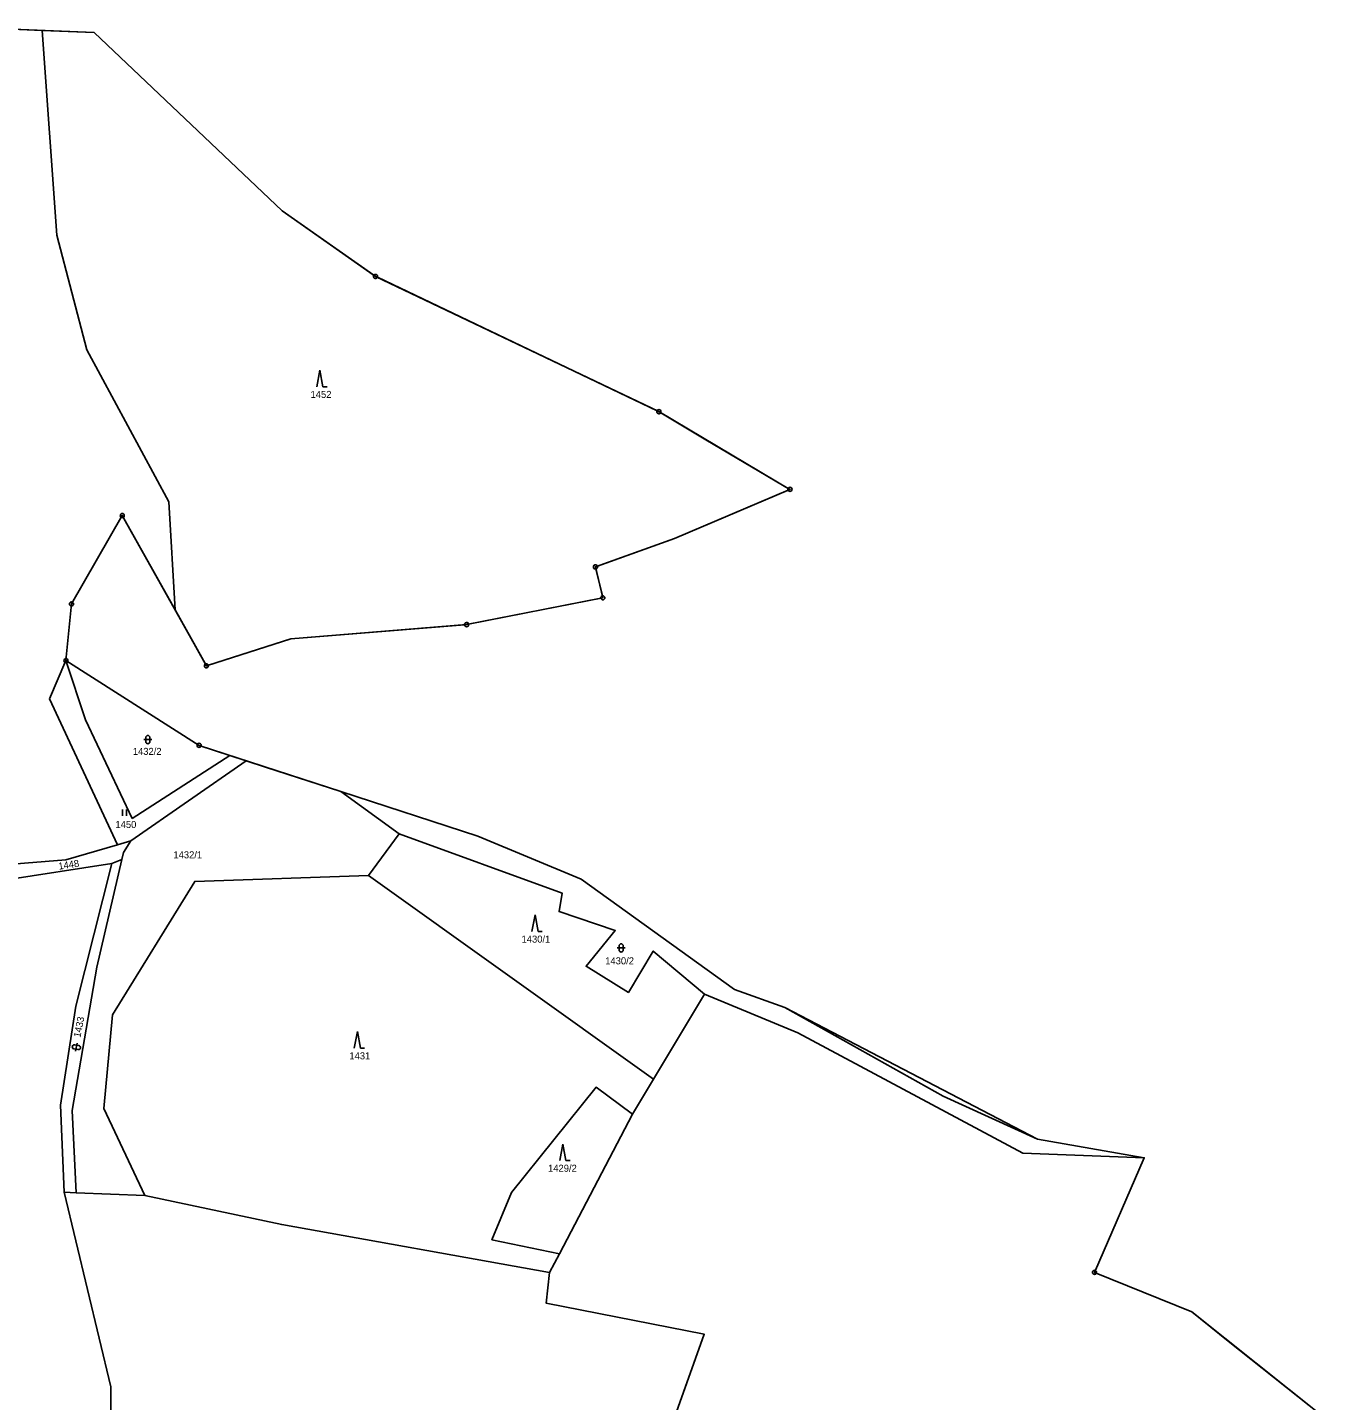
# Model space of a CAD drawing. Extents: x -760642 to -757221, y -1092371 to -1088855.
# Drawn here: x -758872.5 to -758559.6, y -1090656.5 to -1090324.2 of the extents above; entities that cross this region are included whole.
import ezdxf

# ---------------------------------------------------------------- set-up
doc = ezdxf.new("R2010")
doc.units = 0
for name, color, linetype in [('Vrstva 1', 7, 'Continuous'), ('Vrstva 13', 7, 'Continuous'), ('Vrstva 18', 7, 'Continuous'), ('Vrstva 24', 7, 'Continuous'), ('Vrstva 25', 7, 'Continuous'), ('Vrstva 28', 7, 'Continuous'), ('Vrstva 30', 7, 'Continuous')]:
    doc.layers.add(name, color=color, linetype=linetype)

msp = doc.modelspace()

# ---------------------------------------------------------------- linework, layer by layer
at = {"layer": 'Vrstva 1'}
for p, q in [((-758868.91, -1090324.89), (-758865.38, -1090374.41)), ((-758865.38, -1090374.41), (-758858.08, -1090402.2)), ((-758858.08, -1090402.2), (-758838.3, -1090438.95)), ((-758838.3, -1090438.95), (-758836.74, -1090465.14)), ((-758863.16, -1090477.4), (-758867.15, -1090486.69)), ((-758863.16, -1090477.4), (-758858.44, -1090491.77)), ((-758867.15, -1090486.69), (-758850.72, -1090521.98)), ((-758858.44, -1090491.77), (-758847.13, -1090515.61)), ((-758847.13, -1090515.61), (-758823.48, -1090500.36)), ((-758819.57, -1090501.63), (-758847.49, -1090521.03)), ((-758782.53, -1090519.32), (-758796.68, -1090509.09)), ((-758850.72, -1090521.98), (-758847.49, -1090521.03)), ((-758847.49, -1090521.03), (-758849.27, -1090523.84)), ((-758782.53, -1090519.32), (-758789.94, -1090529.44)), ((-758743.09, -1090533.73), (-758782.53, -1090519.32)), ((-758863.21, -1090525.65), (-758850.72, -1090521.98)), ((-758849.27, -1090523.84), (-758849.67, -1090525.57)), ((-758878.15, -1090526.82), (-758863.21, -1090525.65)), ((-758878.13, -1090530.58), (-758852.04, -1090526.51)), ((-758852.04, -1090526.51), (-758860.78, -1090561.07)), ((-758849.67, -1090525.57), (-758855.66, -1090551.59)), ((-758852.04, -1090526.51), (-758849.67, -1090525.57)), ((-758832, -1090530.87), (-758851.93, -1090563.12)), ((-758832, -1090530.87), (-758789.94, -1090529.44)), ((-758789.94, -1090529.44), (-758721.01, -1090578.75)), ((-758743.09, -1090533.73), (-758743.83, -1090538.15)), ((-758743.83, -1090538.15), (-758730.25, -1090542.74)), ((-758730.25, -1090542.74), (-758737.32, -1090551.37)), ((-758721.07, -1090547.7), (-758727.08, -1090557.7)), ((-758721.07, -1090547.7), (-758708.68, -1090558.15)), ((-758855.66, -1090551.59), (-758861.69, -1090586.26)), ((-758737.32, -1090551.37), (-758727.08, -1090557.7)), ((-758708.68, -1090558.15), (-758721.01, -1090578.75)), ((-758708.68, -1090558.15), (-758686.04, -1090567.49)), ((-758860.78, -1090561.07), (-758864.45, -1090585.04)), ((-758851.93, -1090563.12), (-758854, -1090585.82)), ((-758686.04, -1090567.49), (-758631.64, -1090596.66)), ((-758755.34, -1090606.13), (-758734.88, -1090580.69)), ((-758734.88, -1090580.69), (-758726.08, -1090587.22)), ((-758721.01, -1090578.75), (-758726.08, -1090587.22)), ((-758864.45, -1090585.04), (-758863.61, -1090606.09)), ((-758861.69, -1090586.26), (-758860.66, -1090606.2)), ((-758854, -1090585.82), (-758844.04, -1090606.85)), ((-758726.08, -1090587.22), (-758743.77, -1090621)), ((-758631.64, -1090596.66), (-758602.28, -1090597.75)), ((-758863.61, -1090606.09), (-758852.28, -1090653.15)), ((-758860.66, -1090606.2), (-758863.61, -1090606.09)), ((-758844.04, -1090606.85), (-758860.66, -1090606.2)), ((-758844.04, -1090606.85), (-758810.96, -1090613.91)), ((-758760.08, -1090617.58), (-758755.34, -1090606.13)), ((-758810.96, -1090613.91), (-758746.18, -1090625.5)), ((-758743.77, -1090621), (-758760.08, -1090617.58)), ((-758746.18, -1090625.5), (-758743.77, -1090621)), ((-758746.18, -1090625.5), (-758746.95, -1090632.96)), ((-758746.95, -1090632.96), (-758708.72, -1090640.47)), ((-758708.72, -1090640.47), (-758723.71, -1090682.53)), ((-758852.28, -1090653.15), (-758852.35, -1090686.17))]:
    msp.add_line(p, q, dxfattribs=at)
at = {"layer": 'Vrstva 13'}
for p, q in [((-758885.97, -1090324.17), (-758868.91, -1090324.89)), ((-758868.91, -1090324.89), (-758856.34, -1090325.42)), ((-758856.34, -1090325.42), (-758810.83, -1090368.56)), ((-758810.83, -1090368.56), (-758788.26, -1090384.43)), ((-758788.26, -1090384.43), (-758719.69, -1090417.15)), ((-758719.69, -1090417.15), (-758708.32, -1090424.01)), ((-758708.32, -1090424.01), (-758687.98, -1090435.97)), ((-758687.98, -1090435.97), (-758715.88, -1090447.87)), ((-758849.53, -1090442.3), (-758861.82, -1090463.69)), ((-758849.53, -1090442.3), (-758836.74, -1090465.14)), ((-758715.88, -1090447.87), (-758735.04, -1090454.73)), ((-758735.04, -1090454.73), (-758733.26, -1090462.21)), ((-758861.82, -1090463.69), (-758863.16, -1090477.4)), ((-758733.26, -1090462.21), (-758766.23, -1090468.7)), ((-758836.74, -1090465.14), (-758829.17, -1090478.68)), ((-758766.23, -1090468.7), (-758808.75, -1090472.12)), ((-758808.75, -1090472.12), (-758829.17, -1090478.68)), ((-758863.16, -1090477.4), (-758830.94, -1090497.93)), ((-758830.94, -1090497.93), (-758823.48, -1090500.36)), ((-758823.48, -1090500.36), (-758819.57, -1090501.63)), ((-758819.57, -1090501.63), (-758814.86, -1090503.17)), ((-758814.86, -1090503.17), (-758796.68, -1090509.09)), ((-758796.68, -1090509.09), (-758763.51, -1090519.9)), ((-758763.51, -1090519.9), (-758738.51, -1090530.3)), ((-758738.51, -1090530.3), (-758701.38, -1090557.05)), ((-758701.38, -1090557.05), (-758689.24, -1090561.38)), ((-758689.24, -1090561.38), (-758650.92, -1090582.86)), ((-758650.92, -1090582.86), (-758628.1, -1090593.26)), ((-758628.1, -1090593.26), (-758602.28, -1090597.75)), ((-758602.28, -1090597.75), (-758614.29, -1090625.47)), ((-758614.29, -1090625.47), (-758590.74, -1090634.99)), ((-758590.74, -1090634.99), (-758581.97, -1090642.09)), ((-758581.97, -1090642.09), (-758559.61, -1090659.84))]:
    msp.add_line(p, q, dxfattribs=at)
at = {"layer": 'Vrstva 24'}
for centre, radius in [((-758788.26, -1090384.43), 0.5), ((-758788.26, -1090384.43), 0.0327), ((-758719.69, -1090417.15), 0.5), ((-758719.69, -1090417.15), 0.0327), ((-758687.98, -1090435.97), 0.5), ((-758687.98, -1090435.97), 0.0327), ((-758849.53, -1090442.3), 0.5), ((-758849.53, -1090442.3), 0.0327), ((-758735.04, -1090454.73), 0.5), ((-758735.04, -1090454.73), 0.0327), ((-758861.82, -1090463.69), 0.5), ((-758861.82, -1090463.69), 0.0327), ((-758733.26, -1090462.21), 0.5), ((-758733.26, -1090462.21), 0.0327), ((-758766.23, -1090468.7), 0.5), ((-758766.23, -1090468.7), 0.0327), ((-758863.16, -1090477.4), 0.5), ((-758863.16, -1090477.4), 0.0327), ((-758829.17, -1090478.68), 0.5), ((-758829.17, -1090478.68), 0.0327), ((-758830.94, -1090497.93), 0.5), ((-758830.94, -1090497.93), 0.0327), ((-758614.29, -1090625.47), 0.5), ((-758614.29, -1090625.47), 0.0327)]:
    msp.add_circle(centre, radius, dxfattribs=at)
at = {"layer": 'Vrstva 25'}
for p, q in [((-758801.702, -1090407.119), (-758802.435, -1090411.119)), ((-758801.702, -1090407.119), (-758800.969, -1090411.119)), ((-758800.969, -1090411.119), (-758799.969, -1090411.119)), ((-758844.34, -1090496.53), (-758842.34, -1090496.53)), ((-758843.84, -1090497.03), (-758843.84, -1090496.03)), ((-758842.84, -1090497.03), (-758842.84, -1090496.03)), ((-758849.507, -1090513.485), (-758849.507, -1090514.985)), ((-758848.485, -1090514.985), (-758848.485, -1090513.485)), ((-758749.662, -1090538.959), (-758750.395, -1090542.959)), ((-758749.662, -1090538.959), (-758748.929, -1090542.959)), ((-758748.929, -1090542.959), (-758747.929, -1090542.959)), ((-758729.82, -1090546.95), (-758727.82, -1090546.95)), ((-758729.32, -1090547.45), (-758729.32, -1090546.45)), ((-758728.32, -1090547.45), (-758728.32, -1090546.45)), ((-758792.652, -1090567.209), (-758793.385, -1090571.209)), ((-758792.652, -1090567.209), (-758791.919, -1090571.209)), ((-758860.052, -1090570.592), (-758861.033, -1090570.396)), ((-758860.837, -1090571.964), (-758860.444, -1090570.003)), ((-758860.248, -1090571.572), (-758861.229, -1090571.376)), ((-758791.919, -1090571.209), (-758790.919, -1090571.209)), ((-758742.912, -1090594.409), (-758743.645, -1090598.409)), ((-758742.912, -1090594.409), (-758742.179, -1090598.409)), ((-758742.179, -1090598.409), (-758741.179, -1090598.409))]:
    msp.add_line(p, q, dxfattribs=at)
for centre, start, end in [((-758843.34, -1090496.03), 0, 180), ((-758843.34, -1090497.03), 180, 0), ((-758728.82, -1090546.45), 0, 180), ((-758728.82, -1090547.45), 180, 0), ((-758861.131, -1090570.886), 78.68997, 258.68997), ((-758860.15, -1090571.082), 258.68997, 78.68997)]:
    msp.add_arc(centre, 0.5, start, end, dxfattribs=at)
at = {"layer": 'Vrstva 28'}
msp.add_lwpolyline([(-758885.97, -1090324.17), (-758856.34, -1090325.42), (-758810.83, -1090368.56), (-758788.26, -1090384.43), (-758719.69, -1090417.15), (-758687.98, -1090435.97), (-758715.88, -1090447.87), (-758735.04, -1090454.73), (-758733.26, -1090462.21), (-758766.23, -1090468.7), (-758808.75, -1090472.12), (-758829.17, -1090478.68), (-758849.53, -1090442.3), (-758861.82, -1090463.69), (-758863.16, -1090477.4), (-758830.94, -1090497.93), (-758796.68, -1090509.09), (-758763.51, -1090519.9), (-758738.51, -1090530.3), (-758701.38, -1090557.05), (-758689.24, -1090561.38), (-758628.1, -1090593.26), (-758602.28, -1090597.75), (-758614.29, -1090625.47), (-758590.74, -1090634.99), (-758559.61, -1090659.84)], dxfattribs=at)
at = {"layer": 'Vrstva 30'}
for points in [[(-758788.669, -1090384.142), (-758810.83, -1090368.56), (-758856.34, -1090325.42), (-758868.91, -1090324.89), (-758865.38, -1090374.41), (-758858.08, -1090402.2), (-758838.3, -1090438.95), (-758836.74, -1090465.14), (-758829.414, -1090478.244)], [(-758720.141, -1090416.935), (-758787.809, -1090384.645)], [(-758688.411, -1090435.717), (-758708.32, -1090424.01), (-758719.262, -1090417.408)], [(-758734.569, -1090454.561), (-758715.88, -1090447.87), (-758688.44, -1090436.166)], [(-758733.376, -1090461.724), (-758734.924, -1090455.216)], [(-758765.739, -1090468.603), (-758733.751, -1090462.307)], [(-758828.694, -1090478.527), (-758808.75, -1090472.12), (-758766.728, -1090468.74)], [(-758816.526, -1090502.625), (-758819.571, -1090501.633), (-758819.574, -1090501.633), (-758847.49, -1090521.03), (-758849.27, -1090523.84), (-758849.67, -1090525.57), (-758855.66, -1090551.59), (-758861.69, -1090586.26), (-758860.66, -1090606.2), (-758844.04, -1090606.85), (-758854, -1090585.82), (-758851.93, -1090563.12), (-758832, -1090530.87), (-758789.94, -1090529.44), (-758782.53, -1090519.32), (-758796.68, -1090509.09), (-758814.86, -1090503.17), (-758816.526, -1090502.625)], [(-758743.09, -1090533.73), (-758743.83, -1090538.15), (-758730.25, -1090542.74), (-758737.32, -1090551.37), (-758727.08, -1090557.7), (-758721.07, -1090547.7), (-758708.68, -1090558.15), (-758686.04, -1090567.49), (-758631.64, -1090596.66), (-758602.28, -1090597.75), (-758628.1, -1090593.26), (-758650.92, -1090582.86), (-758689.24, -1090561.38), (-758701.38, -1090557.05), (-758738.51, -1090530.3), (-758763.51, -1090519.9), (-758796.68, -1090509.09), (-758782.53, -1090519.32), (-758743.09, -1090533.73)], [(-758789.94, -1090529.44), (-758721.01, -1090578.75), (-758708.68, -1090558.15), (-758721.07, -1090547.7), (-758727.08, -1090557.7), (-758737.32, -1090551.37), (-758730.25, -1090542.74), (-758743.83, -1090538.15), (-758743.09, -1090533.73), (-758782.53, -1090519.32), (-758789.94, -1090529.44)], [(-758760.08, -1090617.58), (-758755.34, -1090606.13), (-758734.88, -1090580.69), (-758726.08, -1090587.22), (-758721.01, -1090578.75), (-758789.94, -1090529.44), (-758832, -1090530.87), (-758851.93, -1090563.12), (-758854, -1090585.82), (-758844.04, -1090606.85), (-758810.96, -1090613.91), (-758746.18, -1090625.5), (-758743.77, -1090621), (-758760.08, -1090617.58)], [(-758734.88, -1090580.69), (-758755.34, -1090606.13), (-758760.08, -1090617.58), (-758743.77, -1090621), (-758726.08, -1090587.22), (-758734.88, -1090580.69)], [(-758821.37, -1090721.67), (-758776.27, -1090726.57), (-758733.29, -1090731.24), (-758725.99, -1090687.96), (-758723.71, -1090682.53), (-758708.72, -1090640.47), (-758746.95, -1090632.96), (-758746.18, -1090625.5), (-758810.96, -1090613.91), (-758844.04, -1090606.85), (-758860.66, -1090606.2), (-758863.61, -1090606.09), (-758852.28, -1090653.15), (-758852.35, -1090686.17), (-758854.21, -1090708.78), (-758858.33, -1090718.54), (-758856.01, -1090718.74), (-758821.37, -1090721.67)]]:
    msp.add_lwpolyline(points, dxfattribs=at)
for centre, start, end in [((-758788.26, -1090384.43), 144.88719, 180), ((-758788.26, -1090384.43), 180, 334.49062), ((-758719.69, -1090417.15), 154.49062, 180), ((-758719.69, -1090417.15), 180, 328.89565), ((-758687.98, -1090435.97), 149.5443, 180), ((-758687.98, -1090435.97), 180, 203.09938), ((-758735.04, -1090454.73), 19.69928, 180), ((-758735.04, -1090454.73), 180, 283.38559), ((-758733.26, -1090462.21), 103.38559, 180), ((-758733.26, -1090462.21), 180, 191.13605), ((-758766.23, -1090468.7), 11.13605, 180), ((-758766.23, -1090468.7), 180, 184.59856), ((-758829.17, -1090478.68), 17.80981, 119.20887)]:
    msp.add_arc(centre, 0.5, start, end, dxfattribs=at)

# ---------------------------------------------------------------- texts
at = {"layer": 'Vrstva 18'}
for s, p in [('1452', (-758803.972, -1090413.83)), ('1432/2', (-758846.977, -1090500.23)), ('1450', (-758851.18, -1090517.92)), ('1432/1', (-758837.155, -1090525.26)), ('1430/1', (-758752.924, -1090545.67)), ('1430/2', (-758732.676, -1090550.92)), ('1431', (-758794.58, -1090573.92)), ('1429/2', (-758746.51, -1090601.12))]:
    msp.add_text(s, height=1.7, dxfattribs=at).set_placement(p)
for s, rotation, p in [('1448', 8.76762, (-758864.86, -1090528.03)), ('1433', 78.69006, (-758859.67, -1090568.73))]:
    msp.add_text(s, height=1.7, rotation=rotation, dxfattribs=at).set_placement(p)

doc.saveas('drawing.dxf')
